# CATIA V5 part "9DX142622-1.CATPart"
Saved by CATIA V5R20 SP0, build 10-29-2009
Part number: 9DX142622-1
Revision: ANY
Definition: UNKNOWN
Nomenclature: 9DX142622-1
Source: Unknown
Bounding box of the stored display mesh (mm): x 0 to 243, y -7.996 to 7.996, z -8 to 7.2
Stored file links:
  C:\Users\Utente\Desktop\IO LAVORO\3D X SITO CF\CUMSA\3D files DX\DX 142622\9DX142622-1.CATPart
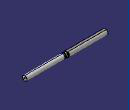
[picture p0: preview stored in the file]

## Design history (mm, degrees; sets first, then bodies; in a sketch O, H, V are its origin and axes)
Body1 "Redondeo1" (main body)
  Solid1: solid without history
